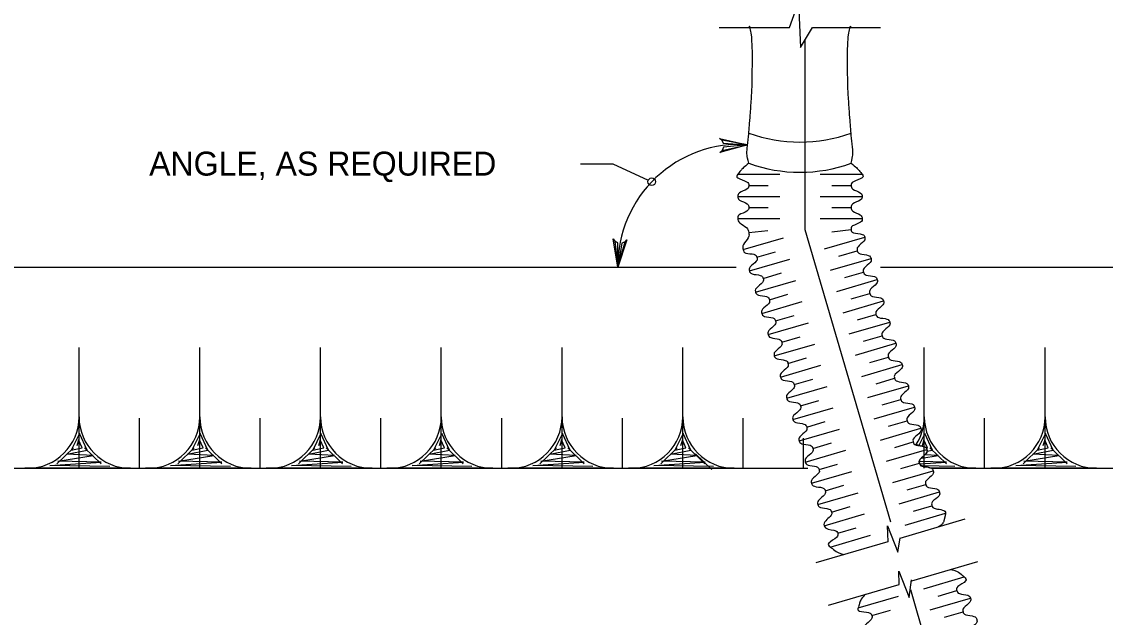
# Model space of a CAD drawing. Extents: x 636462 to 637367, y 299944 to 300538.
# Drawn here: x 636619.2 to 636754.8, y 300354.6 to 300429.2 of the extents above; entities that cross this region are included whole.
import ezdxf

# ---------------------------------------------------------------- set-up
doc = ezdxf.new("R2010")
doc.units = 0
doc.layers.add('Default', color=7, linetype='Continuous')

msp = doc.modelspace()

# ---------------------------------------------------------------- linework, layer by layer
at = {"layer": 'Default'}
for p, q in [((636706.46, 300428.45), (636715.24, 300428.45)), ((636718.12, 300428.45), (636726.65, 300428.45)), ((636717.2, 300426.91), (636717.2, 300403.15)), ((636708.79, 300410.07), (636714.05, 300410.07)), ((636719.09, 300410.07), (636724.35, 300410.07)), ((636710.17, 300408.69), (636712.59, 300408.69)), ((636720.55, 300408.69), (636722.97, 300408.69)), ((636708.79, 300407.3), (636714.05, 300407.3)), ((636719.09, 300407.3), (636724.35, 300407.3)), ((636710.17, 300405.92), (636712.59, 300405.92)), ((636720.55, 300405.92), (636722.97, 300405.92)), ((636708.79, 300404.53), (636714.05, 300404.53)), ((636719.09, 300404.53), (636724.35, 300404.53)), ((636709.47, 300400.64), (636714.52, 300402.12)), ((636710.17, 300402.79), (636712.57, 300403.04)), ((636717.2, 300403.15), (636727.91, 300366.55)), ((636719.63, 300400.73), (636724.68, 300402.21)), ((636720.57, 300402.89), (636722.97, 300403.15)), ((636721.43, 300399.81), (636723.74, 300400.49)), ((636710.24, 300397.98), (636715.29, 300399.46)), ((636711.18, 300399.7), (636713.5, 300400.38)), ((636720.41, 300398.07), (636725.46, 300399.55)), ((636589.35, 300398.45), (636708.58, 300398.45)), ((636722.2, 300397.15), (636724.52, 300397.83)), ((636726.65, 300398.45), (636841.16, 300398.45)), ((636711.02, 300395.32), (636716.07, 300396.8)), ((636711.96, 300397.04), (636714.28, 300397.72)), ((636721.19, 300395.41), (636726.24, 300396.89)), ((636712.74, 300394.38), (636715.06, 300395.06)), ((636722.98, 300394.49), (636725.3, 300395.17)), ((636711.8, 300392.66), (636716.85, 300394.14)), ((636721.97, 300392.75), (636727.02, 300394.23)), ((636713.52, 300391.72), (636715.83, 300392.4)), ((636723.76, 300391.84), (636726.08, 300392.51)), ((636712.58, 300390.01), (636717.63, 300391.48)), ((636722.74, 300390.1), (636727.8, 300391.58)), ((636714.29, 300389.07), (636716.61, 300389.74)), ((636724.54, 300389.18), (636726.86, 300389.86)), ((636626.37, 300373.27), (636626.37, 300388.38)), ((636641.48, 300373.27), (636641.48, 300388.38)), ((636656.58, 300373.27), (636656.58, 300388.38)), ((636671.69, 300373.27), (636671.69, 300388.38)), ((636686.8, 300373.27), (636686.8, 300388.38)), ((636701.91, 300373.27), (636701.91, 300388.38)), ((636713.36, 300387.35), (636718.41, 300388.83)), ((636723.52, 300387.44), (636728.57, 300388.92)), ((636732.13, 300373.27), (636732.13, 300388.38)), ((636747.24, 300373.27), (636747.24, 300388.38)), ((636715.07, 300386.41), (636717.39, 300387.09)), ((636725.32, 300386.52), (636727.63, 300387.2)), ((636714.13, 300384.69), (636719.18, 300386.17)), ((636724.3, 300384.78), (636729.35, 300386.26)), ((636715.85, 300383.75), (636718.17, 300384.43)), ((636726.1, 300383.86), (636728.41, 300384.54)), ((636714.91, 300382.03), (636719.96, 300383.51)), ((636725.08, 300382.12), (636730.13, 300383.6)), ((636716.63, 300381.09), (636718.95, 300381.77)), ((636726.87, 300381.2), (636729.19, 300381.88)), ((636715.69, 300379.37), (636720.74, 300380.85)), ((636725.86, 300379.46), (636730.91, 300380.94)), ((636633.92, 300373.27), (636633.92, 300379.56)), ((636649.03, 300373.27), (636649.03, 300379.56)), ((636664.14, 300373.27), (636664.14, 300379.56)), ((636679.25, 300373.27), (636679.25, 300379.56)), ((636694.36, 300373.27), (636694.36, 300379.56)), ((636709.47, 300373.27), (636709.47, 300379.56)), ((636717.41, 300378.43), (636719.72, 300379.11)), ((636727.65, 300378.55), (636729.97, 300379.22)), ((636739.68, 300373.27), (636739.68, 300379.56)), ((636716.47, 300376.71), (636721.52, 300378.19)), ((636726.63, 300376.8), (636731.69, 300378.28)), ((636717.02, 300373.27), (636717.02, 300377.06)), ((636718.18, 300375.77), (636720.5, 300376.45)), ((636728.43, 300375.89), (636730.75, 300376.57)), ((636731.13, 300376.26), (636731.13, 300376.26)), ((636623.61, 300373.83), (636625.66, 300375.82)), ((636629.13, 300373.83), (636627.07, 300375.82)), ((636629.13, 300373.83), (636627.07, 300375.82)), ((636638.72, 300373.83), (636640.77, 300375.82)), ((636644.23, 300373.83), (636642.18, 300375.82)), ((636644.23, 300373.83), (636642.18, 300375.82)), ((636653.83, 300373.83), (636655.88, 300375.82)), ((636659.34, 300373.83), (636657.29, 300375.82)), ((636659.34, 300373.83), (636657.29, 300375.82)), ((636668.94, 300373.83), (636670.99, 300375.82)), ((636674.45, 300373.83), (636672.4, 300375.82)), ((636674.45, 300373.83), (636672.4, 300375.82)), ((636684.04, 300373.83), (636686.1, 300375.82)), ((636689.56, 300373.83), (636687.51, 300375.82)), ((636689.56, 300373.83), (636687.51, 300375.82)), ((636699.15, 300373.83), (636701.21, 300375.82)), ((636704.67, 300373.83), (636702.62, 300375.82)), ((636704.67, 300373.83), (636702.62, 300375.82)), ((636705.55, 300373.11), (636703.5, 300375.1)), ((636717.24, 300374.06), (636722.29, 300375.54)), ((636727.41, 300374.15), (636732.46, 300375.63)), ((636734.89, 300373.83), (636732.83, 300375.82)), ((636744.48, 300373.83), (636746.53, 300375.82)), ((636750, 300373.83), (636747.94, 300375.82)), ((636750, 300373.83), (636747.94, 300375.82)), ((636718.96, 300373.12), (636721.28, 300373.8)), ((636729.21, 300373.23), (636731.52, 300373.91)), ((636589.35, 300373.27), (636717.54, 300373.27)), ((636632.81, 300373.27), (636619.57, 300373.27)), ((636619.57, 300373.27), (636619.93, 300373.27)), ((636647.92, 300373.27), (636634.68, 300373.27)), ((636634.68, 300373.27), (636635.04, 300373.27)), ((636663.03, 300373.27), (636649.78, 300373.27)), ((636649.78, 300373.27), (636650.14, 300373.27)), ((636678.13, 300373.27), (636664.89, 300373.27)), ((636664.89, 300373.27), (636665.25, 300373.27)), ((636693.24, 300373.27), (636680, 300373.27)), ((636680, 300373.27), (636680.36, 300373.27)), ((636708.35, 300373.27), (636695.11, 300373.27)), ((636695.11, 300373.27), (636695.47, 300373.27)), ((636718.02, 300371.4), (636723.07, 300372.88)), ((636728.19, 300371.49), (636733.24, 300372.97)), ((636738.57, 300373.27), (636732.87, 300373.27)), ((636733.01, 300373.27), (636841.16, 300373.27)), ((636753.68, 300373.27), (636740.44, 300373.27)), ((636740.44, 300373.27), (636740.8, 300373.27)), ((636719.74, 300370.46), (636722.06, 300371.14)), ((636729.98, 300370.57), (636732.3, 300371.25)), ((636718.8, 300368.74), (636723.85, 300370.22)), ((636728.97, 300368.83), (636734.02, 300370.31)), ((636720.52, 300367.8), (636722.84, 300368.48)), ((636730.76, 300367.91), (636733.08, 300368.59)), ((636719.58, 300366.08), (636724.63, 300367.56)), ((636729.1, 300364.54), (636737.25, 300366.93)), ((636729.75, 300366.17), (636734.8, 300367.65)), ((636721.3, 300365.14), (636723.61, 300365.82)), ((636718.6, 300361.47), (636727.6, 300364.1)), ((636720.36, 300363.42), (636725.41, 300364.9)), ((636730.55, 300359.19), (636738.81, 300361.61)), ((636720.15, 300356.15), (636729, 300358.74)), ((636732.08, 300358.2), (636737.13, 300359.68)), ((636723.85, 300355.79), (636728.9, 300357.27)), ((636730.38, 300358.11), (636745.08, 300307.89)), ((636733.87, 300357.28), (636736.19, 300357.96)), ((636732.86, 300355.54), (636737.91, 300357.02)), ((636725.56, 300354.85), (636727.88, 300355.53)), ((636734.65, 300354.62), (636736.97, 300355.3))]:
    msp.add_line(p, q, dxfattribs=at)
for points in [[(636715.24, 300428.45), (636716.37, 300431.59), (636716.62, 300425.94), (636718.12, 300428.45)], [(636706.78, 300414.34), (636706.5, 300414.56), (636710.02, 300413.77), (636706.78, 300414.34), (636706.98, 300413.97), (636710.02, 300413.77), (636707, 300413.45), (636706.82, 300413.07), (636710.02, 300413.77), (636706.55, 300412.81), (636706.82, 300413.07)], [(636689.13, 300411.4), (636693.16, 300411.4), (636697.59, 300409.35)], [(636694.68, 300401.62), (636694.92, 300401.87), (636693.78, 300398.45), (636694.68, 300401.62), (636694.29, 300401.45), (636693.78, 300398.45), (636693.77, 300401.49), (636693.41, 300401.7), (636693.78, 300398.45), (636693.18, 300402), (636693.41, 300401.7)], [(636630.2, 300373.51), (636622.73, 300373.61), (636629.14, 300374.02), (636623.72, 300374.18), (636628.12, 300374.86), (636624.84, 300375.05), (636627.38, 300375.56), (636626.42, 300377.62), (636625.39, 300375.53), (636626.77, 300375.82), (636626.32, 300376.85), (636626.1, 300376.08)], [(636645.31, 300373.51), (636637.83, 300373.61), (636644.25, 300374.02), (636638.83, 300374.18), (636643.22, 300374.86), (636639.95, 300375.05), (636642.49, 300375.56), (636641.52, 300377.62), (636640.5, 300375.53), (636641.88, 300375.82), (636641.43, 300376.85), (636641.2, 300376.08)], [(636660.42, 300373.51), (636652.94, 300373.61), (636659.36, 300374.02), (636653.94, 300374.18), (636658.33, 300374.86), (636655.06, 300375.05), (636657.6, 300375.56), (636656.63, 300377.62), (636655.61, 300375.53), (636656.99, 300375.82), (636656.54, 300376.85), (636656.31, 300376.08)], [(636675.53, 300373.51), (636668.05, 300373.61), (636674.47, 300374.02), (636669.05, 300374.18), (636673.44, 300374.86), (636670.17, 300375.05), (636672.7, 300375.56), (636671.74, 300377.62), (636670.71, 300375.53), (636672.09, 300375.82), (636671.64, 300376.85), (636671.42, 300376.08)], [(636690.64, 300373.51), (636683.16, 300373.61), (636689.58, 300374.02), (636684.16, 300374.18), (636688.55, 300374.86), (636685.28, 300375.05), (636687.81, 300375.56), (636686.85, 300377.62), (636685.82, 300375.53), (636687.2, 300375.82), (636686.75, 300376.85), (636686.53, 300376.08)], [(636705.74, 300373.51), (636698.27, 300373.61), (636704.69, 300374.02), (636699.26, 300374.18), (636703.66, 300374.86), (636700.39, 300375.05), (636702.92, 300375.56), (636701.96, 300377.62), (636700.93, 300375.53), (636702.31, 300375.82), (636701.86, 300376.85), (636701.64, 300376.08)], [(636732.45, 300375.42), (636733.14, 300375.56), (636732.18, 300377.62), (636731.45, 300376.14)], [(636751.07, 300373.51), (636743.6, 300373.61), (636750.01, 300374.02), (636744.59, 300374.18), (636748.98, 300374.86), (636745.71, 300375.05), (636748.25, 300375.56), (636747.28, 300377.62), (636746.26, 300375.53), (636747.64, 300375.82), (636747.19, 300376.85), (636746.96, 300376.08)], [(636732.35, 300375.78), (636732.53, 300375.82), (636732.08, 300376.85), (636731.86, 300376.08)], [(636731.81, 300374.54), (636733.88, 300374.86), (636732.15, 300374.96)], [(636731.58, 300373.81), (636734.9, 300374.02), (636731.54, 300374.12)], [(636735.96, 300373.51), (636732.01, 300373.56)], [(636727.62, 300364.05), (636727.52, 300366.08), (636728.82, 300362.76), (636729.09, 300364.56)], [(636729, 300358.74), (636728.96, 300360.4), (636730.25, 300357.08), (636730.52, 300359.29)]]:
    msp.add_lwpolyline(points, dxfattribs=at)
msp.add_circle((636698.03, 300409.14), 0.481, dxfattribs=at)
for centre, radius, start, end in [((636716.57, 300432.91), 18.8, 250.1065, 289.8935), ((636708.99, 300398.61), 15.2, 86.0884, 180.6016), ((636716.57, 300429.13), 18.8, 250.1065, 289.8935), ((636619.93, 300379.71), 6.44, 270, 0), ((636619.93, 300379.71), 6.44, 270, 0), ((636632.81, 300379.71), 6.44, 180, 270), ((636632.81, 300379.71), 6.44, 180, 270), ((636632.81, 300379.71), 6.44, 180, 270), ((636635.04, 300379.71), 6.44, 270, 0), ((636635.04, 300379.71), 6.44, 270, 0), ((636647.92, 300379.71), 6.44, 180, 270), ((636647.92, 300379.71), 6.44, 180, 270), ((636647.92, 300379.71), 6.44, 180, 270), ((636650.14, 300379.71), 6.44, 270, 0), ((636650.14, 300379.71), 6.44, 270, 0), ((636663.03, 300379.71), 6.44, 180, 270), ((636663.03, 300379.71), 6.44, 180, 270), ((636663.03, 300379.71), 6.44, 180, 270), ((636665.25, 300379.71), 6.44, 270, 0), ((636665.25, 300379.71), 6.44, 270, 0), ((636678.13, 300379.71), 6.44, 180, 270), ((636678.13, 300379.71), 6.44, 180, 270), ((636678.13, 300379.71), 6.44, 180, 270), ((636680.36, 300379.71), 6.44, 270, 0), ((636680.36, 300379.71), 6.44, 270, 0), ((636693.24, 300379.71), 6.44, 180, 270), ((636693.24, 300379.71), 6.44, 180, 270), ((636693.24, 300379.71), 6.44, 180, 270), ((636695.47, 300379.71), 6.44, 270, 0), ((636695.47, 300379.71), 6.44, 270, 0), ((636708.35, 300379.71), 6.44, 180, 270), ((636708.35, 300379.71), 6.44, 180, 270), ((636708.35, 300379.71), 6.44, 180, 270), ((636725.69, 300379.71), 6.44, 327.6292, 0), ((636725.69, 300379.71), 6.44, 327.6292, 0), ((636738.57, 300379.71), 6.44, 180, 270), ((636738.57, 300379.71), 6.44, 180, 270), ((636740.8, 300379.71), 6.44, 270, 0), ((636740.8, 300379.71), 6.44, 270, 0), ((636753.68, 300379.71), 6.44, 180, 270), ((636753.68, 300379.71), 6.44, 180, 270), ((636753.68, 300379.71), 6.44, 180, 270)]:
    msp.add_arc(centre, radius, start, end, dxfattribs=at)
for points, degree in [([(636710.17, 300411.46), (636710.04, 300411.98), (636709.91, 300412.51), (636709.95, 300413.04), (636710.01, 300413.77), (636710.12, 300414.5), (636710.17, 300415.23), (636710.23, 300415.97), (636710.29, 300416.71), (636710.35, 300417.45), (636710.42, 300418.46), (636710.49, 300419.47), (636710.55, 300420.48), (636710.6, 300421.49), (636710.6, 300422.5), (636710.61, 300423.51), (636710.63, 300424.68), (636710.61, 300425.84), (636710.55, 300427), (636710.52, 300427.5), (636710.23, 300428.94), (636710.22, 300428.45)], 3), ([(636722.97, 300411.46), (636723.1, 300411.98), (636723.23, 300412.51), (636723.19, 300413.04), (636723.13, 300413.77), (636723.02, 300414.5), (636722.97, 300415.23), (636722.91, 300415.97), (636722.85, 300416.71), (636722.79, 300417.45), (636722.72, 300418.46), (636722.65, 300419.47), (636722.59, 300420.48), (636722.54, 300421.49), (636722.54, 300422.5), (636722.53, 300423.51), (636722.51, 300424.68), (636722.53, 300425.84), (636722.59, 300427), (636722.62, 300427.5), (636722.91, 300428.94), (636722.92, 300428.45)], 3), ([(636710.17, 300411.46), (636709.56, 300410.99), (636709.12, 300410.53), (636708.79, 300410.07), (636708.46, 300409.61), (636710.17, 300409.15), (636710.17, 300408.69), (636710.17, 300408.22), (636708.79, 300407.76), (636708.79, 300407.3), (636708.79, 300406.84), (636710.19, 300406.38), (636710.17, 300405.92), (636710.16, 300405.45), (636708.73, 300404.99), (636708.79, 300404.53), (636708.86, 300404.01), (636710.07, 300403.39), (636710.17, 300402.79), (636710.27, 300402.18), (636709.33, 300401.25), (636709.47, 300400.64), (636709.58, 300400.11), (636711.02, 300400.15), (636711.18, 300399.7), (636711.34, 300399.24), (636710.11, 300398.42), (636710.24, 300397.98), (636710.37, 300397.54), (636711.83, 300397.48), (636711.96, 300397.04), (636712.09, 300396.6), (636710.89, 300395.76), (636711.02, 300395.32), (636711.15, 300394.88), (636712.61, 300394.82), (636712.74, 300394.38), (636712.87, 300393.94), (636711.67, 300393.11), (636711.8, 300392.66), (636711.93, 300392.22), (636713.39, 300392.17), (636713.52, 300391.72), (636713.65, 300391.28), (636712.45, 300390.45), (636712.58, 300390.01), (636712.71, 300389.56), (636714.16, 300389.51), (636714.29, 300389.07), (636714.42, 300388.62), (636713.23, 300387.79), (636713.36, 300387.35), (636713.49, 300386.9), (636714.94, 300386.85), (636715.07, 300386.41), (636715.2, 300385.96), (636714, 300385.13), (636714.13, 300384.69), (636714.26, 300384.25), (636715.72, 300384.19), (636715.85, 300383.75), (636715.98, 300383.31), (636714.78, 300382.47), (636714.91, 300382.03), (636715.04, 300381.59), (636716.5, 300381.53), (636716.63, 300381.09), (636716.76, 300380.65), (636715.56, 300379.82), (636715.69, 300379.37), (636715.82, 300378.93), (636717.28, 300378.88), (636717.41, 300378.43), (636717.54, 300377.99), (636716.34, 300377.16), (636716.47, 300376.71), (636716.6, 300376.27), (636718.05, 300376.22), (636718.18, 300375.77), (636718.31, 300375.33), (636717.11, 300374.5), (636717.24, 300374.06), (636717.37, 300373.61), (636718.83, 300373.56), (636718.96, 300373.12), (636719.09, 300372.67), (636717.89, 300371.84), (636718.02, 300371.4), (636718.15, 300370.96), (636719.61, 300370.9), (636719.74, 300370.46), (636719.87, 300370.02), (636718.67, 300369.18), (636718.8, 300368.74), (636718.93, 300368.3), (636720.39, 300368.24), (636720.52, 300367.8), (636720.65, 300367.36), (636719.45, 300366.53), (636719.58, 300366.08)], 3), ([(636722.97, 300411.46), (636723.58, 300410.99), (636724.02, 300410.53), (636724.35, 300410.07), (636724.68, 300409.61), (636722.97, 300409.15), (636722.97, 300408.69), (636722.97, 300408.22), (636724.35, 300407.76), (636724.35, 300407.3), (636724.35, 300406.84), (636722.97, 300406.38), (636722.97, 300405.92), (636722.97, 300405.45), (636724.33, 300404.99), (636724.35, 300404.53), (636724.38, 300404.07), (636722.9, 300403.61), (636722.97, 300403.15), (636723.03, 300402.68), (636724.59, 300402.61), (636724.68, 300402.21), (636724.78, 300401.8), (636723.62, 300400.93), (636723.74, 300400.49), (636723.87, 300400.05), (636725.33, 300399.99), (636725.46, 300399.55), (636725.59, 300399.11), (636724.39, 300398.27), (636724.52, 300397.83), (636724.65, 300397.39), (636726.11, 300397.33), (636726.24, 300396.89), (636726.37, 300396.45), (636725.17, 300395.62), (636725.3, 300395.17), (636725.43, 300394.73), (636726.89, 300394.68), (636727.02, 300394.23), (636727.15, 300393.79), (636725.95, 300392.96), (636726.08, 300392.51), (636726.21, 300392.07), (636727.67, 300392.02), (636727.8, 300391.58), (636727.93, 300391.13), (636726.73, 300390.3), (636726.86, 300389.86), (636726.99, 300389.41), (636728.44, 300389.36), (636728.57, 300388.92), (636728.7, 300388.47), (636727.5, 300387.64), (636727.63, 300387.2), (636727.76, 300386.76), (636729.22, 300386.7), (636729.35, 300386.26), (636729.48, 300385.82), (636728.28, 300384.98), (636728.41, 300384.54), (636728.54, 300384.1), (636730, 300384.04), (636730.13, 300383.6), (636730.26, 300383.16), (636729.06, 300382.33), (636729.19, 300381.88), (636729.32, 300381.44), (636730.78, 300381.39), (636730.91, 300380.94), (636731.04, 300380.5), (636729.84, 300379.67), (636729.97, 300379.22), (636730.1, 300378.78), (636731.56, 300378.73), (636731.69, 300378.28), (636731.82, 300377.84), (636730.62, 300377.01), (636730.75, 300376.57), (636730.87, 300376.12), (636732.33, 300376.07), (636732.46, 300375.63), (636732.59, 300375.18), (636731.39, 300374.35), (636731.52, 300373.91), (636731.65, 300373.46), (636733.11, 300373.41), (636733.24, 300372.97), (636733.37, 300372.52), (636732.17, 300371.69), (636732.3, 300371.25), (636732.43, 300370.81), (636733.89, 300370.75), (636734.02, 300370.31), (636734.15, 300369.87), (636732.95, 300369.03), (636733.08, 300368.59), (636733.21, 300368.15), (636734.88, 300368.07), (636734.8, 300367.65)], 3), ([(636732.87, 300373.27), (636732.39, 300373.47), (636731.62, 300373.59), (636731.52, 300373.91), (636731.39, 300374.35), (636732.59, 300375.18), (636732.46, 300375.63), (636732.37, 300375.94), (636731.61, 300376.06), (636731.13, 300376.26)], 3), ([(636734.8, 300367.65), (636734.71, 300367.23), (636734.47, 300366.22), (636733.86, 300365.93)], 2), ([(636719.58, 300366.08), (636719.71, 300365.64), (636721.17, 300365.59), (636721.3, 300365.14), (636721.43, 300364.7), (636719.84, 300363.84), (636720.36, 300363.42), (636720.87, 300363.01), (636721.44, 300362.67), (636722.07, 300362.48)], 3), ([(636735.41, 300360.62), (636736.07, 300360.52), (636736.63, 300360.13), (636737.13, 300359.68), (636737.63, 300359.23), (636736.06, 300358.4), (636736.19, 300357.96), (636736.32, 300357.52), (636737.78, 300357.46), (636737.91, 300357.02), (636738.04, 300356.58), (636736.84, 300355.74), (636736.97, 300355.3), (636737.1, 300354.86), (636738.56, 300354.8), (636738.69, 300354.36), (636738.82, 300353.92), (636737.62, 300353.08), (636737.75, 300352.64), (636737.88, 300352.2), (636739.33, 300352.14), (636739.46, 300351.7), (636739.59, 300351.26), (636738.39, 300350.43), (636738.52, 300349.99), (636738.65, 300349.54), (636740.11, 300349.49), (636740.24, 300349.04), (636740.37, 300348.6), (636739.17, 300347.77), (636739.3, 300347.33), (636739.43, 300346.88), (636740.89, 300346.83), (636741.02, 300346.39), (636741.15, 300345.94), (636739.95, 300345.11), (636740.08, 300344.67), (636740.21, 300344.22), (636741.67, 300344.17), (636741.8, 300343.73), (636741.93, 300343.28), (636740.73, 300342.45), (636740.86, 300342.01), (636740.99, 300341.57), (636742.71, 300341.53), (636742.58, 300341.07), (636742.44, 300340.61), (636742.16, 300339.77), (636741.64, 300339.35)], 3), ([(636724.79, 300357.51), (636724.26, 300357.09), (636723.98, 300356.25), (636723.85, 300355.79), (636723.71, 300355.33), (636725.43, 300355.29), (636725.56, 300354.85), (636725.69, 300354.41), (636724.49, 300353.57), (636724.62, 300353.13), (636724.75, 300352.69), (636726.21, 300352.63), (636726.34, 300352.19), (636726.47, 300351.75), (636725.27, 300350.91), (636725.4, 300350.47), (636725.53, 300350.03), (636726.99, 300349.97), (636727.12, 300349.53), (636727.25, 300349.09), (636726.05, 300348.26), (636726.18, 300347.82), (636726.31, 300347.37), (636727.77, 300347.32), (636727.9, 300346.88), (636728.03, 300346.43), (636726.83, 300345.6), (636726.96, 300345.16), (636727.09, 300344.71), (636728.55, 300344.66), (636728.68, 300344.22), (636728.81, 300343.77), (636727.61, 300342.94), (636727.74, 300342.5), (636727.87, 300342.05), (636729.32, 300342), (636729.45, 300341.56), (636729.58, 300341.11), (636728.38, 300340.28), (636728.51, 300339.84), (636728.64, 300339.4), (636730.1, 300339.34), (636730.23, 300338.9), (636730.36, 300338.46), (636728.79, 300337.63), (636729.29, 300337.18), (636729.79, 300336.73), (636730.36, 300336.34), (636731.01, 300336.24)], 3)]:
    msp.add_open_spline(points, degree=degree, dxfattribs=at)

# ---------------------------------------------------------------- texts
msp.add_text('ANGLE, AS REQUIRED', height=2.998, dxfattribs=at).set_placement((636635.14, 300409.91))

doc.saveas('drawing.dxf')
